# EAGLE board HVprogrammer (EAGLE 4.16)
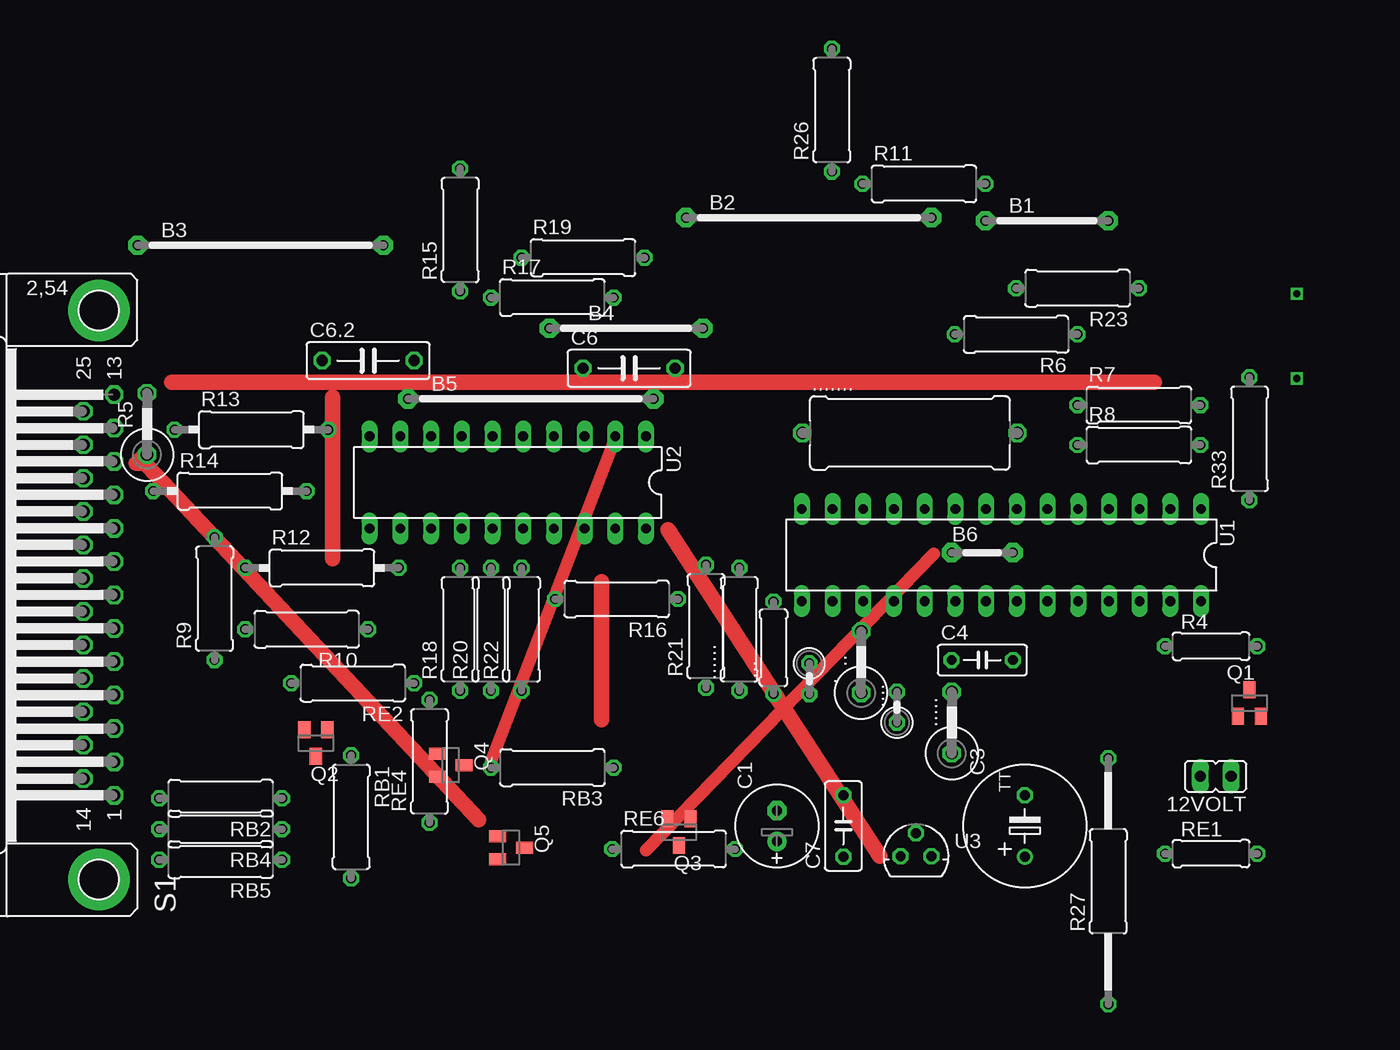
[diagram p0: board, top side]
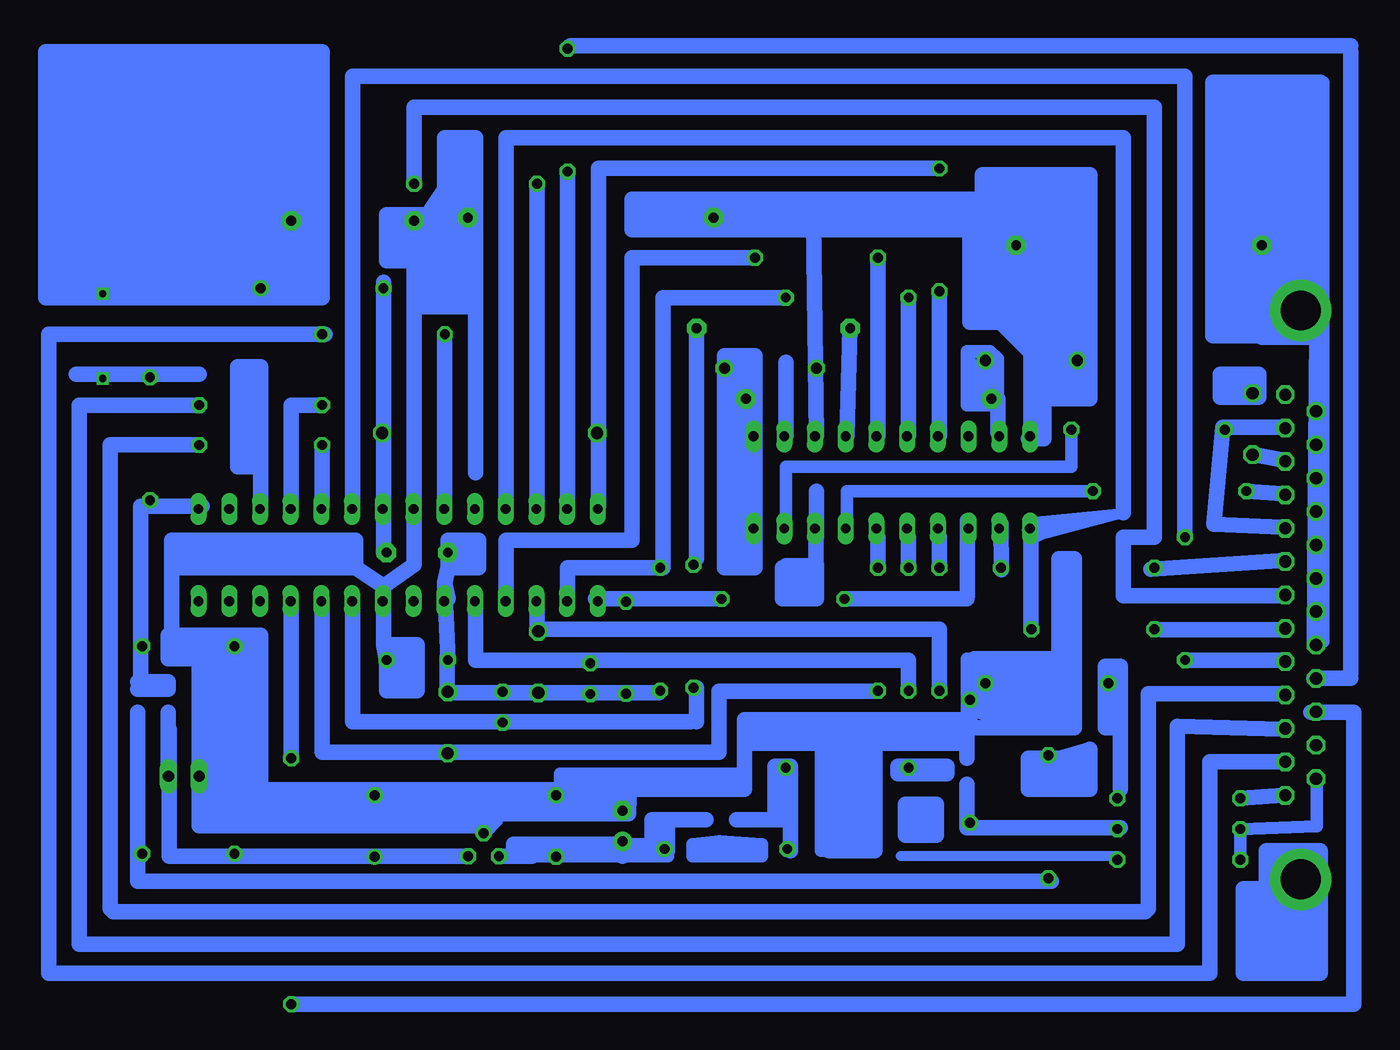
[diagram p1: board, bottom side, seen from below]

No outline drawn. Coordinates in mm, seen from the top.
Copper layers (1*16): Top 0.035mm / dielectric 1.5mm / Bottom 0.035mm
Design rules "default": minimum track width 10mil, minimum drill 24mil, track to track 8mil, track to pad 8mil, pad to pad 8mil, via to via 8mil, smd to smd 8mil, copper to edge 40mil, drill to drill 8mil, minimum pad ring 10mil, minimum via ring 8mil, stop-mask expansion 4mil, vias tented up to drill 0mil, thermal gap 10mil

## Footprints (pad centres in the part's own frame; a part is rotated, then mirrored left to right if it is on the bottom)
JP1 = drill 0.914 long: 1 0,-1.27; 2 0,1.27
0207/2V = drill 0.813 octagon: 1 -1.27,0; 2 1.27,0
0414V = drill 1.016 octagon: 1 -2.54,0; 2 2.54,0
0207/7 = drill 0.813 octagon: 1 -3.81,0; 2 3.81,0
0309/10 = drill 0.813 octagon: 1 -5.08,0; 2 5.08,0
0617/17 = drill 1.016 octagon: 1 -8.89,0; 2 8.89,0
10 = drill 0.813 pad 1.6 octagon: 1 -5.08,0; 2 5.08,0
20 = drill 0.813 pad 1.6 octagon: 1 -10.16,0; 2 10.16,0
12 = drill 0.813 pad 1.6 octagon: 1 -6.35,0; 2 6.35,0
05 = drill 0.813 pad 1.6 octagon: 1 -2.54,0; 2 2.54,0
E2,5-7 = drill 0.813 pad 1.6 round: + -1.27,0 | drill 0.813 pad 1.6 octagon: - 1.27,0
TT5D10 = drill 0.813 round: + -2.54,0 | drill 0.813 octagon: - 2.54,0
C050-025X075 = drill 0.813 octagon: 1 -2.54,0; 2 2.54,0
C075-032X103 = drill 0.914 octagon: 1 -3.81,0; 2 3.81,0
C050-030X075 = drill 0.813 octagon: 1 -2.54,0; 2 2.54,0
SOT23 = smd 1 x 1.4: 1 -0.95,-1.1; 2 0.95,-1.1; 3 0,1.1
0309/12 = drill 0.813 octagon: 1 -6.35,0; 2 6.35,0
0309/20 = drill 0.813 octagon: 1 -10.16,0; 2 10.16,0
F25HP = drill 1.016 octagon: 1 -16.561,-1.27; 2 -13.792,-1.27; 3 -11.049,-1.27; 4 -8.28,-1.27; 5 -5.512,-1.27; 6 -2.769,-1.27; 7 0,-1.27; 8 2.769,-1.27; 9 5.512,-1.27; 10 8.28,-1.27; 11 11.049,-1.27; 12 13.792,-1.27; 13 16.561,-1.27; 14 -15.189,1.27; 15 -12.421,1.27; 16 -9.652,1.27; 17 -6.909,1.27; 18 -4.14,1.27; 19 -1.372,1.27; 20 1.372,1.27; 21 4.14,1.27; 22 6.909,1.27; 23 9.652,1.27; 24 12.421,1.27; 25 15.189,1.27 | drill 3.302 pad 5.08 round: G1 -23.52,0; G2 23.52,0
DIL28-3 = drill 0.813 long: 1 -16.51,-3.81; 2 -13.97,-3.81; 3 -11.43,-3.81; 4 -8.89,-3.81; 5 -6.35,-3.81; 6 -3.81,-3.81; 7 -1.27,-3.81; 8 1.27,-3.81; 9 3.81,-3.81; 10 6.35,-3.81; 11 8.89,-3.81; 12 11.43,-3.81; 13 13.97,-3.81; 14 16.51,-3.81; 15 16.51,3.81; 16 13.97,3.81; 17 11.43,3.81; 18 8.89,3.81; 19 6.35,3.81; 20 3.81,3.81; 21 1.27,3.81; 22 -1.27,3.81; 23 -3.81,3.81; 24 -6.35,3.81; 25 -8.89,3.81; 26 -11.43,3.81; 27 -13.97,3.81; 28 -16.51,3.81
DIL20 = drill 0.813 long: 1 -11.43,-3.81; 2 -8.89,-3.81; 3 -6.35,-3.81; 4 -3.81,-3.81; 5 -1.27,-3.81; 6 1.27,-3.81; 7 3.81,-3.81; 8 6.35,-3.81; 9 8.89,-3.81; 10 11.43,-3.81; 11 11.43,3.81; 12 8.89,3.81; 13 6.35,3.81; 14 3.81,3.81; 15 1.27,3.81; 16 -1.27,3.81; 17 -3.81,3.81; 18 -6.35,3.81; 19 -8.89,3.81; 20 -11.43,3.81
78LXX = drill 0.813 octagon: GND 0,1.905; IN 1.27,0; OUT -1.27,0

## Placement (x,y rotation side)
12VOLT  [JP1]  97.79,20.11 90 top
.  [0207/2V]  64.18,28.18 270 top
..  [0414V]  68.47,29.55 90 top
...  100k  [0207/7]  61.21,30.73 90 top
....  [0207/2V]  71.43,25.82 90 top
.....  100k  [0414V]  75.97,24.55 90 top
......  100k  [0309/10]  58.39,32.26 90 top
.......  100k  [0617/17]  72.5,48.5 0 top
B1  [10]  83.82,66.04 0 top
B2  [20]  64.14,66.29 0 top
B3  [20]  18.8,64.01 0 top
B4  [12]  49.03,57.15 0 top
B5  [20]  41.15,51.31 0 top
B6  [05]  78.49,38.61 0 top
C1  10µ  [E2,5-7]  61.5,16 90 top
C3  100µ  [TT5D10]  82,16 90 top
C4  10n  [C050-025X075]  78.49,29.72 0 top
C6  74HC299  [C075-032X103]  49.28,53.85 0 top
C6.2  100n  [C075-032X103]  27.69,54.48 0 top
C7  100n  [C050-030X075]  67,16 90 top
Q1  PNP  [SOT23]  100.58,26.16 0 top
Q2  NPN  [SOT23]  23.37,22.86 180 top
Q3  PNP  [SOT23]  53.41,15.49 180 top
Q4  NPN  [SOT23]  34.52,21.03 270 top
Q5  PNP  [SOT23]  39.51,14.22 270 top
R4  4k7  [0207/7]  97.41,30.86 0 top
R5  100  [0414V]  9.41,49.24 90 top
R6  1k  [0309/10]  81.28,56.64 180 top
R7  1k  [0309/10]  91.44,50.8 0 top
R8  1k  [0309/10]  91.44,47.5 0 top
R9  1k  [0309/10]  14.99,34.8 90 top
R10  1k  [0309/10]  22.61,32.26 180 top
R11  1k  [0309/10]  73.66,69.09 0 top
R12  1k  [0309/12]  23.88,37.34 0 top
R13  1k  [0309/12]  18.03,48.77 0 top
R14  100  [0309/12]  16.26,43.69 0 top
R15  1k  [0309/10]  35.31,65.28 90 top
R16  1k  [0309/10]  48.24,34.77 180 top
R17  1k  [0309/10]  42.93,59.69 0 top
R18  1k  [0309/10]  35.31,32.26 90 top
R19  1k  [0309/10]  45.47,62.99 0 top
R20  1k  [0309/10]  37.85,32.26 90 top
R21  1k  [0309/10]  55.63,32.51 90 top
R22  1k  [0309/10]  40.39,32.26 90 top
R23  680  [0309/10]  86.36,60.45 180 top
R26  1k  [0309/10]  66.04,75.18 90 top
R27  1k  [0309/20]  88.9,11.43 90 top
R33  4k7  [0309/10]  100.58,48.01 90 top
RB1  10k  [0309/10]  26.29,16.76 270 top
RB2  10k  [0309/10]  15.49,18.29 180 top
RB3  10k  [0309/10]  42.93,20.83 180 top
RB4  10k  [0309/10]  15.49,15.75 180 top
RB5  47  [0309/10]  15.49,13.21 180 top
RE1  10k  [0207/7]  97.41,13.72 0 top
RE2  10k  [0309/10]  26.42,27.81 180 top
RE4  10k  [0309/10]  32.77,21.34 90 top
RE6  10k  [0309/10]  52.96,14.1 0 top
S1  Centronics  [F25HP]  5.42,35.1 90 top
U1  28pin  [DIL28-3]  80.06,38.4 180 top
U2  74HC299  [DIL20]  39.24,44.4 180 top
U3  78L05  [78LXX]  73,13.5 0 top

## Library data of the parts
12VOLT B1-B6 = jumper
. .. ... .... ..... ...... ....... C1 C4 C6 C6.2 C7 R4-R23 R26 R27 R33 RB1-RB5 RE1 RE2 RE4 RE6 = rcl
C3 = ref-packages
Q1-Q5 = transistor-npn
S1 = con-subd
U1 U2 = 40xx
U3 = v-reg

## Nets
S$10: R15.2
S$13: C4.2
S$14: R17.2
S$16: R18.1
S$17: R19.2
S$18: R22.1
S$19: R20.1
S$21: R15.1
S$22: R17.1
S$23: R19.1
S$26: R18.2
S$27: R20.2
S$28: R22.2
S$31: B4.2
S$32: C6.2
S$38: R26.1
S$44: R11.1
S$49: R9.1
S$50: R11.2
S$51: R6.2
S$52: C4.1
S$55: R8.1
S$57: R7.1
S$62: R7.2
S$67: R8.2
S$70: 12VOLT.1
S$106: B4.1

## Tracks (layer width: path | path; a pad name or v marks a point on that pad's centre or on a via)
CENTRONICS
  Bottom 1.27: 4.57,25.4 1.02,25.4 1.02,1.27 30.23,1.27
S$1
  Bottom 1.27: 6.91,40.71 12.59,40.96 11.84,48.97 6.61,48.97
S$2
  Bottom 1.27: 6.61,37.97 17.83,37.21
S$3
  Bottom 1.27: 30.18,37.17 30.22,41
S$4
  Bottom 1.016: 24.38,48.77 24.38,45.72 48.01,45.72 48.01,40.64
S$5
  Bottom 1.27: 6.91,32.24 16.95,32.24
S$6
  Bottom 0.406: 27.73,40.46 28.28,40.46
  Bottom 1.27: 27.73,32.24 27.74,32.28 27.73,40.46
S$7
  Bottom 1.016: 4.42,31.35 4.17,62.32
S$8
  Bottom 1.27: 6.91,43.49 9.9,43.66
S$9
  Bottom 1.016: 42.93,40.64 42.93,43.69 22.61,43.69
S$10
  Bottom 1.27: R15.2 63.5,70.36 63.5,42.42
S$11
  Bottom 1.27: 45.47,39.88 45.47,43.69
S$12
  Bottom 1.27: 33.02,34.8 43.18,34.8
S$13
  Bottom 1.27: 77.98,59.44 77.98,66.29 76.96,67.06 76.96,59.18 75.95,59.18 75.95,68.33 74.68,68.33 74.68,59.18 73.91,58.93 78.74,58.93 | 74.93,72.89 76.2,72.89 76.2,68.58 74.93,68.58 74.93,72.89 | 74.93,72.89 73.66,72.89 73.66,68.58 | 73.66,68.58 73.66,45.21 | 73.66,68.58 73.66,69.09 75.95,69.09 78.49,65.28 | 78.49,66.55 79.76,66.55 | 78.49,66.55 77.22,66.55 | 79.76,66.55 81.03,66.55 81.03,64.01 | 78.49,65.28 78.49,66.55 | 79.76,64.01 79.76,66.55 | 81.03,64.01 81.03,62.74 79.76,62.74 | 79.76,62.74 79.76,64.01 | 78.49,64.01 78.49,65.28 | 78.49,64.01 81.03,64.01 | 78.49,64.01 79.76,64.01 | 98.81,38.61 98.81,39.62 96.27,39.62 | 98.81,37.34 98.81,30.99 | 98.81,37.34 98.81,38.61 | 96.27,38.61 83.57,38.61 | 96.27,38.61 96.27,39.62 | 96.27,38.61 98.81,38.61 | 78.74,62.74 78.49,64.01 | 78.74,62.74 79.76,62.74 | 78.74,58.93 78.74,62.74 | 96.27,37.34 96.27,38.61 | 96.27,37.34 98.81,37.34 | 96.27,39.62 83.57,39.62 83.57,37.34 | 83.57,37.34 96.27,37.34 | 78.74,58.93 78.74,37.59 81.28,35.82 | 81.28,35.82 83.57,37.34 | 81.28,30.99 81.28,35.82 | 81.28,30.99 C4.2 | C4.2 81.03,27.18 79.76,27.18 | 79.76,29.72 C4.2 | 79.76,27.18 79.76,29.72 | 81.28,30.99 78.49,30.99 78.49,27.18 | 79.76,29.72 78.49,29.72 78.49,27.18 | 78.49,27.18 79.76,27.18
S$14
  Bottom 1.27: R17.2 58.17,59.69 58.17,37.34 66.04,37.34 66.04,34.8
S$15
  Bottom 1.27: 20.32,15.88 33.02,15.88 33.02,19.43
S$16
  Bottom 1.27: R18.1 35.31,32.26 68.58,32.26 68.58,34.8
S$17
  Bottom 1.27: R19.2 60.71,62.99 60.71,39.62 71.12,39.62 71.12,34.8
S$18
  Bottom 1.27: 86.36,34.8 86.36,22.1 53.55,22.1 53.55,27.14 40.39,27.14 R22.1
S$19
  Bottom 1.27: 73.66,34.8 73.66,29.72 37.85,29.72 R20.1
S$20
  Bottom 1.27: 4.45,10.79 4.45,12.06 5.08,12.06
S$21
  Bottom 1.27: 35.31,48.26 R15.1
S$22
  Bottom 1.27: 37.85,48.26 R17.1
S$23
  Bottom 1.27: 40.39,48.26 R19.1
S$24
  Bottom 1.27: 88.9,21.59 88.9,34.8
S$25
  Bottom 1.27: 33,41.25 33,35
S$26
  Bottom 1.27: 35.31,39.88 R18.2
S$27
  Bottom 1.27: 37.85,39.88 R20.2
S$28
  Bottom 1.27: 40.39,39.88 R22.2
S$29
  Bottom 1.27: 83.82,34.8 83.82,24.64 55.86,24.64
S$30
  Bottom 1.27: 30.23,1.27 88.65,1.27
S$31
  Bottom 1.27: B4.2 55.38,38.1
S$32
  Bottom 1.27: 50.55,47.5 50.55,48.77 51.82,48.77 | 50.55,41.15 50.55,47.5 | 50.55,41.15 50.55,39.88 51.82,39.88 | 51.82,48.77 53.09,48.77 53.09,47.5 | 53.09,46.23 53.09,47.5 | 53.09,39.88 53.09,46.23 | 51.82,39.88 53.09,39.88 | 51.82,48.77 53.09,46.23 | 50.55,47.5 50.55,51.31 C6.2 50.55,54.86 51.82,54.86 | 51.82,54.86 53.09,54.86 53.09,47.5 | 51.82,39.88 51.82,54.86 | 53.09,39.88 53.09,37.34 51.82,37.34 | 51.82,37.34 50.55,37.34 50.55,41.15 | 51.82,37.34 51.82,39.88
S$33
  Bottom 1.27: 30.48,48.51 30.48,51.31
S$34
  Bottom 1.27: 48.01,48.26 48.01,54.36
S$35
  Bottom 1.27: 81.28,38.61 81.28,60.96
S$36
  Bottom 1.016: 4.07,19.55 4.07,16 10.41,15.75 10.41,13.21
S$37
  Bottom 1.27: 1.27,80.52 65.79,80.52
S$38
  Bottom 1.27: 66.04,42.42 R26.1
S$39
  Bottom 1.27: 86.11,56.64 108.97,56.64 108.97,3.82 12.95,3.82 12.95,21.33 6.87,21.33
S$40
  Bottom 1.27: 1.27,28.19 4.32,28.19
S$41
  Bottom 1.27: 96.27,42.42 101.35,42.42 101.35,27.68
S$42
  Bottom 1.27: 26.04,11.43 101.6,11.43 101.6,25.4
S$43
  Bottom 1.27: 50.55,54.61 50.55,50.8
S$44
  Bottom 1.27: R11.1 68.58,42.42
S$45
  Bottom 1.27: 20.32,19.05 20.32,24.13 | 20.32,24.13 20.32,29.21 21.59,29.21 21.59,24.13 20.32,24.13
S$46
  Bottom 0.813: 27.69,39.88 20.07,41.91 27.69,41.15
  Bottom 1.27: 20.07,41.91 20.07,72.9 71.12,72.9 71.12,42.42 | 27.69,39.88 25.15,41.15
S$47
  Bottom 1.27: 83.82,42.42 83.82,77.98 14.99,77.98 14.99,40.13
S$48
  Bottom 1.27: 27.73,48.13 27.73,62.32
S$49
  Bottom 1.27: 6.86,29.72 R9.1
S$50
  Bottom 1.27: 6.6,35.05 20.07,35.05 20.07,39.88 17.53,39.88 17.53,75.44 78.74,75.44 R11.2
S$51
  Bottom 1.27: 76.2,42.67 R6.2
S$52
  Bottom 1.27: 76.2,36.07 75.95,37.34 | 76.2,36.07 75.95,34.8 | C4.1 76.2,36.07 | 75.95,37.34 74.68,37.34 | 74.68,37.34 73.41,37.34 73.41,39.62 74.68,39.62 | 74.68,39.62 75.95,39.62 75.95,37.34 | 74.68,39.62 74.68,37.34
S$53
  Bottom 1.016: 3.81,62.23 3.81,67.31
  Bottom 1.27: 7.62,77.47 10.16,77.47 | 10.16,77.47 12.7,77.47 | 7.62,77.47 7.62,66.04 | 6.35,77.47 6.35,67.31 5.08,67.31 5.08,77.47 | 6.35,77.47 7.62,77.47 | 5.08,77.47 6.35,77.47 | 5.08,77.47 3.81,77.47 3.81,67.31 | 6.35,56.52 7.62,56.52 | 8.89,56.52 11.43,56.52 | 11.43,56.52 12.7,56.52 12.7,77.47 | 12.7,77.47 11.43,77.47 11.43,56.52 | 11.43,56.52 10.16,56.52 10.16,77.47 | 10.16,77.47 8.89,77.47 8.89,56.52 | 8.89,56.52 7.62,56.52 | 7.62,56.52 7.62,62.23
S$54
  Bottom 1.27: 6.87,18.53 10.41,18.28
S$55
  Bottom 1.27: 86.36,42.42 R8.1
S$56
  Bottom 1.016: 3.56,31.24 3.56,77.47 6.1,67.82
  Bottom 1.27: 6.1,62.74 8.64,62.74 | 4.83,62.74 6.1,62.74 | 8.64,61.47 8.64,62.74 | 8.64,61.47 8.64,56.39 4.83,56.39 4.83,62.74 | 6.1,62.74 6.1,61.47 | 6.1,61.47 6.1,56.39 | 4.83,62.74 4.83,64.01 8.64,64.01 | 8.64,62.74 8.64,64.01 | 8.64,64.01 8.64,65.28 4.83,65.28 | 4.83,62.74 4.83,65.28 | 4.83,65.28 4.83,66.55 | 4.83,66.55 8.64,66.55 8.64,64.01 | 8.64,64.01 8.64,67.82 6.1,67.82 4.83,67.82 4.83,66.55 | 8.64,61.47 6.1,61.47
S$57
  Bottom 1.27: 88.9,42.16 88.9,50.8 R7.1
S$58
  Bottom 1.27: 91.44,42.55 91.44,53.98 93.34,53.98 93.34,45.72 92.71,45.72 | 92.08,45.72 92.71,45.72 | 92.71,45.72 92.71,53.34
S$59
  Bottom 1.27: 25.4,21.59 25.4,19.05 | 25.4,21.59 22.86,22.34 22.86,20.32 | 25.4,21.59 27.94,21.59 27.94,20.32 | 22.86,20.32 22.86,19.05 27.94,19.05 27.94,20.32 | 22.86,20.32 27.94,20.32
S$60
  Bottom 1.27: 106.68,53.34 96.52,53.34
S$61
  Bottom 1.27: 101.6,27.3 99.06,27.3 99.06,27.94 101.6,27.94
S$62
  Bottom 1.27: R7.2 106.43,50.8 106.43,49.78
S$63
  Bottom 1.27: 6.96,24 15.63,24.25 15.63,6.24
S$64  (via drill 0.6)
  other vias: 104.5,60
S$65
  Bottom 1.27: 6.85,46.23 9.39,46.73
S$66
  Bottom 1.27: 15.63,6.24 106.45,6.24 106.45,50.51
S$67
  Bottom 1.27: R8.2 103.89,47.5 103.89,9.14
S$68
  Bottom 1.27: 6.62,26.92 18.03,26.92 18.03,9.14
S$69
  Bottom 1.27: 18.28,8.89 103.64,8.89
S$70
  Bottom 1.27: 12VOLT.1 99.06,25.4
S$71
  Bottom 1.27: 99,24 99,13.5 74.5,13.5
S$72
  Top 1.27: 46.99,36.2 46.99,24.77
S$73
  Bottom 1.016: 70.5,13.5 61.5,13.5 57.73,13.5 57.73,14.5 61.5,14.5
  Bottom 1.27: 70.5,13.5 71.5,13.5 | 69,14.5 69,13.5 70.5,13.5 | 69,14.5 61.5,14.5 61.5,13.5 | 69,14.5 70.5,14.5 70.5,13.5
S$74
  Bottom 1.27: 91.5,21.5 96.5,21.5 96.5,20.5 | 96.5,20.5 91.5,20.5 | 96.5,20 96.5,20.5 | 96.5,20 91.5,20 | 96.5,19.5 96.5,20 | 96.5,19.5 96,19 92,19 | 92,19 91.5,19 | 96.5,17.5 77,17.5 77,16.5 95.5,16.5 96,17 96,18 76.5,18 | 96.5,17.5 96.5,19.5 | 96.5,17.5 96.5,16 76.5,16 | 76.5,19 92,19 | 76.5,19 66.65,19 73,18 | 73,15.5 73.5,16 76.5,16 | 73,15.5 72,16.5 | 76.5,18 76.5,19 | 76.5,17 76.5,16 | 76.5,17 76.5,18 | 73,18 73,15.5 | 73,18 76.5,18 | 73,18 73,17.5 73.5,17 | 61,18 61,18.5 | 61,18 73,18 | 73.5,17 76.5,17 | 73.5,17 61,17 61,18
S$75
  Bottom 1.016: 53.48,14.75 55.73,14.5 55.73,13.5 53.23,13.5 | 53.48,14.75 52.23,14.5 52.23,13.5 53.23,13.5 | 53.48,14.75 49.96,14.5 49.96,13.5 53.23,13.5
S$76
  Top 1.016: 50.69,14 74.5,38.5
S$77
  Top 1.27: 70,13.5 52.5,40.5
S$78
  Bottom 1.27: 34.67,20.95 38.73,20.95 38.73,20.32 34.67,20.32 34.67,20.95
S$79
  Bottom 1.27: 91.44,19.68 91.44,31.75 98.42,31.75 98.42,31.11 99.06,31.75 99.06,29.84 96.52,29.84 96.52,20.95
S$80
  Bottom 1.016: 45.09,22.86 45.09,13.97 44.45,13.97
  Bottom 1.27: 41.27,13.97 40.64,13.97 40.64,24.13 | 41.27,13.97 41.91,13.97 41.91,22.86 | 44.45,24.13 50.8,24.13 | 44.45,24.13 44.45,22.86 | 40.64,24.13 44.45,24.13 | 41.91,22.86 43.18,22.86 | 44.45,22.86 50.8,22.86 | 31.75,26.67 30.48,26.67 | 31.75,26.67 31.75,27.94 25.4,27.94 25.4,26.67 | 31.75,26.67 31.75,25.4 29.21,25.4 | 29.21,26.67 25.4,26.67 | 29.21,26.67 31.75,26.67 | 33.02,22.86 33.02,21.61 | 33.02,22.86 41.91,22.86 | 36.83,24.13 38.1,24.13 | 36.83,24.13 40.64,24.13 | 33.02,24.13 36.83,24.13 | 33.02,24.13 33.02,22.86 | 29.21,25.4 29.21,26.67 | 25.4,26.67 24.13,26.67 24.13,25.4 | 24.13,25.4 29.21,25.4 | 29.21,24.13 33.02,24.13 | 29.21,24.13 29.21,25.4 | 29.21,24.13 24.13,24.13 24.13,25.4 | 41.27,13.97 43.18,13.97 | 43.18,13.97 43.18,22.86 | 43.18,22.86 44.45,22.86 | 44.45,22.86 45.09,22.86 | 43.18,13.97 44.45,13.97 44.45,22.86
S$81
  Bottom 0.813: 20.5,13.5 38.5,13.5
S$82
  Bottom 1.27: 36.83,15.24 38.1,15.24 38.1,17.78 35.56,17.78 | 36.83,15.24 35.56,15.24 | 35.56,15.24 35.56,17.78 | 35.56,17.78 36.83,17.78 36.83,16.51 | 36.83,16.51 36.83,15.24 | 36.83,15.24 35.56,16.51 36.83,16.51 | 36.83,16.51 35.56,15.24
S$83
  Bottom 1.016: 33.02,28.57 33.02,29.21
S$84
  Bottom 1.27: 91,66.5 93,66.5 93,63 90,63 90,66.5 91,66.5 | 91,66.5 91,63.5 92,63.5 92,66
S$85
  Top 1.27: 9,46 8.5,46
S$86
  Top 1.27: 8.89,46.35 36.83,16.51
S$87
  Top 1.016: 48,47.69 37.84,21.35
S$88
  Top 1.27: 11.43,52.7 92.71,52.7
S$89
  Bottom 1.016: 32.77,24.89 51.05,24.89
  Bottom 1.27: 24.38,26.16 24.13,26.16 24.13,28.45 32.77,28.45 32.77,24.89
S$90
  Bottom 1.27: 1.27,28.57 1.27,80.01
S$91
  Bottom 1.27: 87.63,67.31 88.9,67.31 | 88.9,67.31 93.98,67.31 93.98,62.23 | 93.98,60.96 93.98,59.69 | 93.98,59.69 88.9,59.69 | 87.63,59.69 86.36,59.69 | 86.36,59.69 86.36,67.31 87.63,67.31 | 87.63,67.31 87.63,59.69 | 87.63,59.69 88.9,59.69 | 88.9,59.69 88.9,60.96 | 88.9,60.96 88.9,62.23 | 88.9,67.31 88.9,62.23 | 88.9,62.23 93.98,62.23 | 93.98,62.23 93.98,60.96 | 93.98,60.96 88.9,60.96 | 109.22,78.74 109.22,80.01 86.36,80.01 86.36,78.74 | 109.22,77.47 109.22,78.74 | 109.22,73.66 109.22,74.93 | 109.22,71.12 109.22,72.39 | 109.22,69.85 109.22,68.58 | 109.22,68.58 109.22,59.69 107.95,59.69 | 106.68,59.69 107.95,59.69 | 102.87,59.69 104.14,59.69 | 100.33,59.69 101.6,59.69 | 97.79,59.69 99.06,59.69 | 97.79,59.69 97.16,59.69 | 97.16,59.69 96.52,59.69 96.52,68.58 | 96.52,68.58 96.52,69.85 87.63,69.85 | 86.36,76.2 86.36,77.47 | 86.36,74.93 86.36,76.2 | 86.36,72.39 86.36,73.66 | 86.36,70.48 86.36,69.85 97.79,69.85 | 86.36,70.48 86.36,71.12 | 99.06,69.85 101.6,69.85 | 101.6,69.85 102.87,69.85 | 104.14,69.85 105.41,69.85 | 109.22,69.85 106.68,69.85 | 109.22,71.12 109.22,69.85 | 100.33,71.12 109.22,71.12 | 100.33,71.12 86.36,71.12 | 86.36,71.12 86.36,72.39 | 86.36,72.39 109.22,72.39 | 109.22,72.39 109.22,73.66 | 86.36,73.66 109.22,73.66 | 86.36,73.66 86.36,74.93 | 86.36,74.93 109.22,74.93 | 109.22,76.2 109.22,77.47 | 86.36,77.47 109.22,77.47 | 86.36,77.47 86.36,78.74 | 86.36,78.74 109.22,78.74 | 109.22,76.2 109.22,78.74 | 109.22,74.93 109.22,76.2 | 86.36,76.2 109.22,76.2 | 97.79,59.69 97.79,69.85 | 97.79,69.85 99.06,69.85 | 99.06,59.69 99.06,69.85 | 99.06,59.69 100.33,59.69 | 100.33,59.69 100.33,71.12 | 100.33,71.12 101.6,69.85 | 101.6,59.69 101.6,69.85 | 101.6,59.69 102.87,59.69
  Bottom 1.27: 102.87,69.85 102.87,59.69 | 102.87,69.85 104.14,69.85 | 104.14,59.69 104.14,69.85 | 104.14,59.69 105.41,59.69 | 105.41,59.69 106.68,59.69 | 106.68,59.69 106.68,68.58 | 106.68,69.85 106.68,68.58 | 105.41,69.85 106.68,69.85 | 105.41,69.85 105.41,59.69 | 105.41,59.69 107.95,59.69 | 107.95,59.69 107.95,68.58 | 109.22,68.58 106.68,68.58 | 86.36,59.69 86.36,70.48 | 86.36,70.48 87,70.48 87,68.58 | 87,67.94 87,68.58 | 87,68.58 94.61,68.58 | 94.61,68.58 95.25,68.58 | 96.52,68.58 95.25,68.58 | 95.25,68.58 95.25,59.69 97.16,59.69 | 97.16,59.69 93.98,59.69 | 93.98,59.69 94.61,59.69 94.61,68.58
S$92  (via drill 0.6)
  other vias: 104.5,53
S$93
  Bottom 1.016: 51.44,20.32 66.67,20.32 66.67,19.05
  Bottom 1.27: 60.96,17.78 60.96,19.05 | 60.96,19.68 60.96,19.05 | 50.8,24.77 51.44,24.77 51.44,21.59 | 51.44,21.59 51.44,20.32 | 66.67,17.78 66.67,19.05 61.59,19.05 | 60.96,19.05 61.59,19.05 | 51.44,21.59 51.44,19.05 61.59,19.05
S$94
  Bottom 1.27: 47.62,13.97 47.62,16.51 | 47.62,16.51 47.62,20.95 48.9,20.95 48.9,16.51 | 52.07,16.51 48.9,16.51 | 48.9,16.51 47.62,16.51
S$95
  Bottom 1.27: 76,30 76,27 58.5,27
S$96
  Bottom 1.016: 30.48,50.8 31.75,50.8 | 33.02,50.8 33.02,52.07 | 33.02,52.07 33.02,55.24 | 30.48,54.61 30.48,52.07 | 33.02,52.07 31.75,50.8 | 31.75,50.8 31.75,53.34 | 31.75,53.34 31.75,54.61 | 31.75,54.61 31.11,55.24 | 33.02,55.24 33.02,50.8 | 33.02,50.8 31.75,50.8 | 31.75,50.8 33.02,55.24 | 33.02,55.24 31.11,55.24 | 31.11,55.24 30.48,54.61 | 30.48,54.61 30.48,50.8 | 30.48,50.8 31.75,54.61 | 31.75,54.61 30.48,54.61 | 31.75,53.34 30.48,54.61
S$97
  Bottom 1.27: 45.5,41 45.5,37.5 48,37.5
S$98
  Bottom 1.27: 98.42,30.48 94.61,30.48 | 93.34,30.48 92.08,30.48 92.08,21.59 93.34,21.59 93.34,30.48 | 93.34,30.48 94.61,30.48 | 94.61,30.48 94.61,21.59 95.89,21.59 | 95.89,21.59 95.89,20.95 | 95.89,21.59 95.89,31.11
S$99
  Bottom 1.27: 53.34,34.8 63.75,34.8
S$100
  Bottom 1.27: 45.47,37.59 45.47,34.8 48.26,34.8 48.26,37.34 47.24,37.34 47.24,35.31 46.23,35.31 46.23,36.83
S$101
  Bottom 1.27: 27.94,48.01 26.67,48.01 26.67,51.31 22.86,51.31 22.86,52.07 | 30.48,67.31 26.67,67.31 | 25.4,67.31 24.13,67.31 | 24.13,67.31 22.86,67.31 | 22.86,67.31 22.86,52.07 | 22.86,52.07 24.13,52.07 | 25.4,52.07 26.67,52.07 26.67,67.31 | 26.67,67.31 25.4,67.31 | 25.4,67.31 25.4,52.07 | 25.4,52.07 24.13,52.07 | 24.13,52.07 24.13,67.31 | 22.86,67.31 22.86,68.58 31.75,68.58 31.75,69.85 22.86,69.85 22.86,67.31
S$102
  Bottom 1.27: 60.71,65.28 60.45,65.53 | 28.96,67.82 27.69,67.82 27.69,55.12 | 30.23,67.82 31.5,67.82 | 32.77,67.82 40.39,67.82 | 40.39,67.82 42.93,67.82 | 27.69,55.12 27.69,53.85 | 27.69,55.12 28.96,56.39 | 28.96,56.39 30.23,57.66 | 31.5,57.66 32.77,57.66 32.77,66.55 | 32.77,67.82 32.77,66.55 | 31.5,67.82 32.77,67.82 | 31.5,57.66 31.5,67.82 | 30.23,57.66 31.5,57.66 | 30.23,57.66 30.23,67.82 | 28.96,67.82 30.23,67.82 | 28.96,56.39 28.96,67.82 | 40.39,67.82 53.59,67.82 | 53.59,67.82 55.63,67.82 | 53.59,67.82 60.71,67.82 60.71,65.28 | 60.71,65.28 31.24,65.28 31.24,65.53 | 32.77,66.55 60.45,66.55
S$103
  Bottom 1.27: 4.45,3.81 3.81,3.81 3.81,13.97 4.45,13.97 | 5.08,3.81 6.35,3.81 | 7.62,3.81 8.26,3.81 | 9.53,3.81 10.16,3.81 10.16,10.79 8.26,10.79 8.26,13.97 6.35,13.97 | 5.71,13.97 4.45,13.97 | 4.45,13.97 4.45,3.81 | 4.45,3.81 5.08,3.81 | 5.08,3.81 5.71,3.81 5.71,13.97 | 5.71,13.97 6.35,13.97 | 6.35,13.97 6.35,3.81 | 6.35,3.81 7.62,3.81 | 7.62,3.81 7.62,13.34 8.26,13.34 8.26,3.81 | 8.26,3.81 9.53,3.81 | 9.53,3.81 9.53,10.16
S$104
  Bottom 1.27: 45.47,48.26 45.72,66.04
S$105
  Bottom 1.27: 7.62,56.52 6.99,56.52 6.99,63.5
S$106
  Bottom 1.27: 42.93,48.26 B4.1
S$107
  Bottom 1.27: 55.38,24.63 55.38,27.44
S$108
  Bottom 1.016: 22.75,21.48 22.75,21.5
S$109
  Bottom 1.27: 8.89,52.07 8.89,53.34 12.06,53.34 12.06,51.44 8.89,51.44 8.89,52.07 | 8.89,52.07 10.16,52.07 10.16,52.7 11.43,52.7
S$110
  Bottom 1.27: 23,21.5 24.25,21.5 24.25,20.25
S$111
  Top 1.27: 24.77,51.44 24.77,38.1
S$112
  Bottom 1.016: 66.04,19.68 52.07,19.68
S$113
  Bottom 1.27: 59.05,14.61 59.05,16.51 57.78,16.51 | 57.78,13.97 57.78,16.51 | 57.78,16.51 54.61,16.51
S$114
  Bottom 1.016: 33.02,25.4 33.02,29.84 25.4,29.84 | 25.4,29.21 31.75,29.21
  Bottom 1.27: 32.38,28.57 32.38,29.84 25.4,29.84 | 25.4,29.84 24.77,29.84 | 24.13,28.57 24.13,38.1 25.4,38.1 25.4,29.84 | 25.4,29.84 25.4,29.21 25.4,28.57
S$115
  Bottom 1.27: 55.5,14 50.25,14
